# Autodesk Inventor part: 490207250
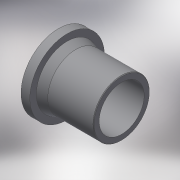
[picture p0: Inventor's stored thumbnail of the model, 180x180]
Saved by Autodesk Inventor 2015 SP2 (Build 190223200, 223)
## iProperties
Created: 2017-07
Part Number: 490207250
Material: Generic
Description: Stub Flange 250
Document SubType Name: Modeling
Designer: Кирилл
Mass: 5116.62 g
Surface Area: 4107.4 cm^2
Volume: 5116.62 cm^3
Density: 1 g/cm^3
Appearance: Default
Author: Кирилл
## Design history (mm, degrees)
derived "490207.ipt"
feature "Solid1::490207.ipt"
tag "TaggingFeature1"
body "Solid1"
other parameters: "d0" = 215, "d1" = 285, "d5" = 35, "d6" = 145, "d17" = 5, "d18" = 5, "d19" = 5, "d21" = 5, "d24" = 5, "d25" = 5, "d26" = 2.5, "d27" = 0, "d32" = 2.5, "L_" = 215, "L_1" = 145, "D_1" = 285, "a_" = 35
